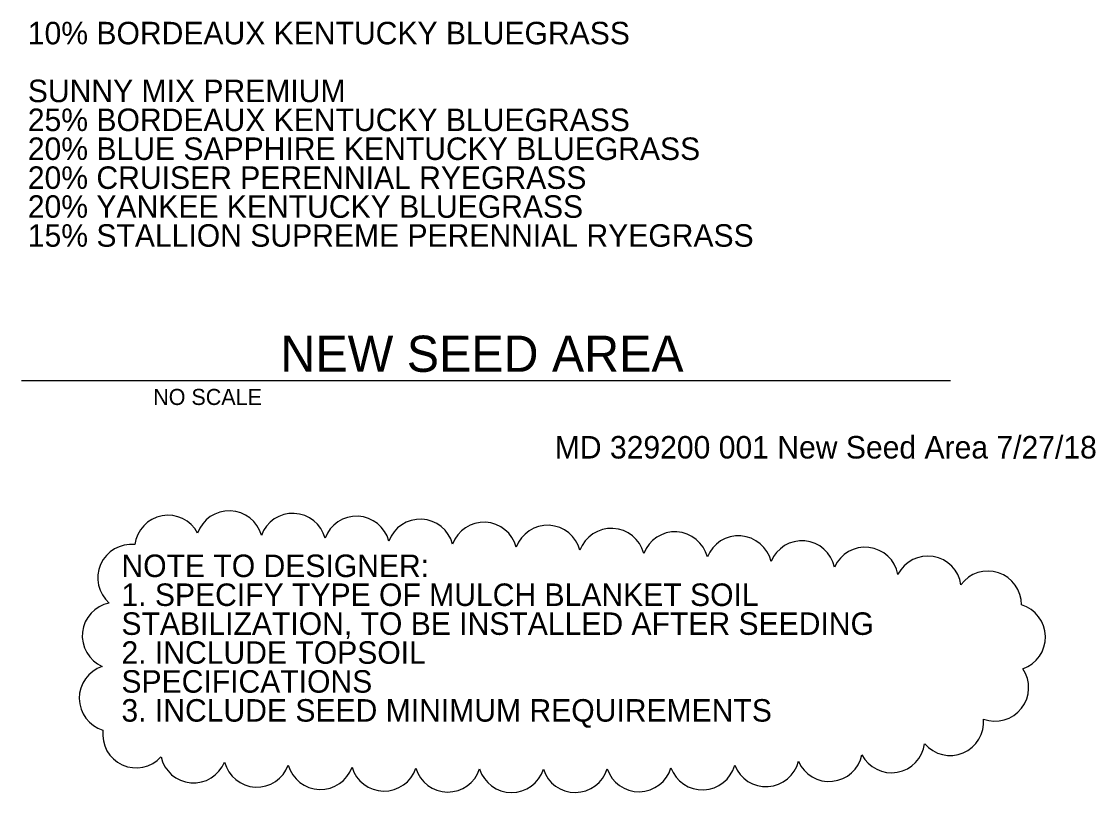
# Model space of a CAD drawing. Extents: x 9915.7 to 9955.7, y 9888.6 to 9936.3.
# Drawn here: x 9920.98 to 9954.38, y 9888.56 to 9912.54 of the extents above; entities that cross this region are included whole.
import ezdxf

# ---------------------------------------------------------------- set-up
doc = ezdxf.new("R2010")
doc.units = 0
for name, color, linetype in [('G-ANNO-CELL', 7, 'Continuous'), ('G-ANNO-TEXT', 7, 'Continuous'), ('G-DETL-GRID', 7, 'Continuous'), ('G-DETL-TEXT', 7, 'Continuous')]:
    doc.layers.add(name, color=color, linetype=linetype)

msp = doc.modelspace()

# ---------------------------------------------------------------- linework, layer by layer
at = {"layer": 'G-ANNO-TEXT'}
msp.add_line((9920.976, 9901.374), (9949.869, 9901.374), dxfattribs=at)
at = {"layer": 'G-DETL-TEXT'}
for centre, start, end in [((9925.535, 9896.142), 27.9255, 172.9255), ((9927.435, 9896.282), 15.4981, 160.4981), ((9929.415, 9896.203), 14.9773, 159.9773), ((9931.396, 9896.114), 14.8572, 159.8572), ((9933.378, 9896.022), 14.7942, 159.7942), ((9935.36, 9895.927), 14.7536, 159.7536), ((9937.341, 9895.832), 14.7247, 159.7247), ((9939.323, 9895.735), 14.6871, 159.6871), ((9941.302, 9895.63), 14.2569, 159.2569), ((9943.278, 9895.505), 13.5136, 158.5136), ((9924.389, 9895.236), 83.724, 228.724), ((9945.251, 9895.35), 12.4798, 157.4798), ((9947.216, 9895.15), 10.898, 155.898), ((9949.164, 9894.875), 8.0045, 153.0045), ((9951.038, 9894.41), 359.1263, 144.1263), ((9923.907, 9893.434), 101.3236, 246.3236), ((9951.786, 9893.396), 288.7138, 73.7138), ((9923.813, 9891.493), 108.1048, 253.1048), ((9951.263, 9891.822), 249.5055, 34.5055), ((9949.863, 9890.752), 220.259, 5.259), ((9924.543, 9890.369), 172.9352, 317.9352), ((9948.037, 9890.216), 207.4915, 352.4915), ((9946.096, 9889.946), 203.344, 348.344), ((9926.33, 9889.901), 192.6961, 337.6961), ((9928.298, 9889.771), 194.7604, 339.7604), ((9930.275, 9889.695), 195.7881, 340.7881), ((9942.157, 9889.684), 199.6479, 344.6479), ((9944.131, 9889.783), 201.1021, 346.1021), ((9932.255, 9889.646), 196.4334, 341.4334), ((9934.237, 9889.617), 196.887, 341.887), ((9936.219, 9889.602), 197.2458, 342.2458), ((9938.2, 9889.604), 197.8167, 342.8167), ((9940.18, 9889.628), 198.6077, 343.6077)]:
    msp.add_arc(centre, 1.04, start, end, dxfattribs=at)

# ---------------------------------------------------------------- texts
at = {"layer": 'G-ANNO-CELL'}
for s, height, p in [('NO SCALE', 0.5, (9925.073, 9900.613)), ('MD 329200 001 New Seed Area 7/27/18', 0.7, (9937.563, 9898.948))]:
    msp.add_text(s, height=height, dxfattribs=at).set_placement(p)
at = {"layer": 'G-ANNO-TEXT'}
for s, p in [('10% BORDEAUX KENTUCKY BLUEGRASS', (9921.173, 9911.828)), ('SUNNY MIX PREMIUM', (9921.173, 9910.03)), ('25% BORDEAUX KENTUCKY BLUEGRASS', (9921.173, 9909.131)), ('20% BLUE SAPPHIRE KENTUCKY BLUEGRASS', (9921.173, 9908.232)), ('20% CRUISER PERENNIAL RYEGRASS', (9921.173, 9907.333)), ('20% YANKEE KENTUCKY BLUEGRASS', (9921.173, 9906.434)), ('15% STALLION SUPREME PERENNIAL RYEGRASS', (9921.173, 9905.534))]:
    msp.add_text(s, height=0.7, dxfattribs=at).set_placement(p)
at = {"layer": 'G-DETL-GRID'}
msp.add_text('NEW SEED AREA', height=1.125, dxfattribs=at).set_placement((9929.032, 9901.644))
at = {"layer": 'G-DETL-TEXT'}
for s, p in [('NOTE TO DESIGNER:', (9924.085, 9895.262)), ('1. SPECIFY TYPE OF MULCH BLANKET SOIL ', (9924.085, 9894.363)), ('STABILIZATION, TO BE INSTALLED AFTER SEEDING', (9924.085, 9893.464)), ('2. INCLUDE TOPSOIL ', (9924.085, 9892.565)), ('SPECIFICATIONS', (9924.085, 9891.666)), ('3. INCLUDE SEED MINIMUM REQUIREMENTS', (9924.085, 9890.766))]:
    msp.add_text(s, height=0.7, dxfattribs=at).set_placement(p)

doc.saveas('drawing.dxf')
